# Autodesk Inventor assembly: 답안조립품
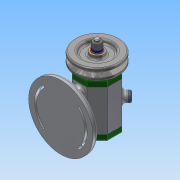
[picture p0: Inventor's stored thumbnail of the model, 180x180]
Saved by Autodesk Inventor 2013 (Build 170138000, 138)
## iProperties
Created: 2017-06
Part Number: 답안조립품
Document SubType Name: Assembly
Designer: Administrator
Author: Administrator
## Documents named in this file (14)
- C:\Users\Administrator\Desktop\470608V1011\답안조립품.iam
- C:\Users\Administrator\Desktop\470608V1011\본체.ipt
- C:\Users\Administrator\Desktop\470608V1011\V벨트풀리.ipt
- C:\Users\Administrator\Desktop\470608V1011\고무캡.ipt
- C:\Users\Administrator\Desktop\470608V1011\너트 M 8.ipt
- C:\Users\Administrator\Desktop\470608V1011\뒤커버.ipt
- C:\Users\Administrator\Desktop\470608V1011\베어링 15 x 32 x 9.ipt
- C:\Users\Administrator\Desktop\470608V1011\볼트 M4 x 12.ipt
- C:\Users\Administrator\Desktop\470608V1011\스프링와셔 8.ipt
- C:\Users\Administrator\Desktop\470608V1011\앞커버.ipt
- C:\Users\Administrator\Desktop\470608V1011\오일 실 15 25 7.ipt
- C:\Users\Administrator\Desktop\470608V1011\와셔 8x17.ipt
- C:\Users\Administrator\Desktop\470608V1011\축.ipt
- C:\Users\Administrator\Desktop\470608V1011\키 3 x 3 x 12.ipt
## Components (2 placed, 2 different names)
1. V벨트풀리:1
2. 고무캡:1
